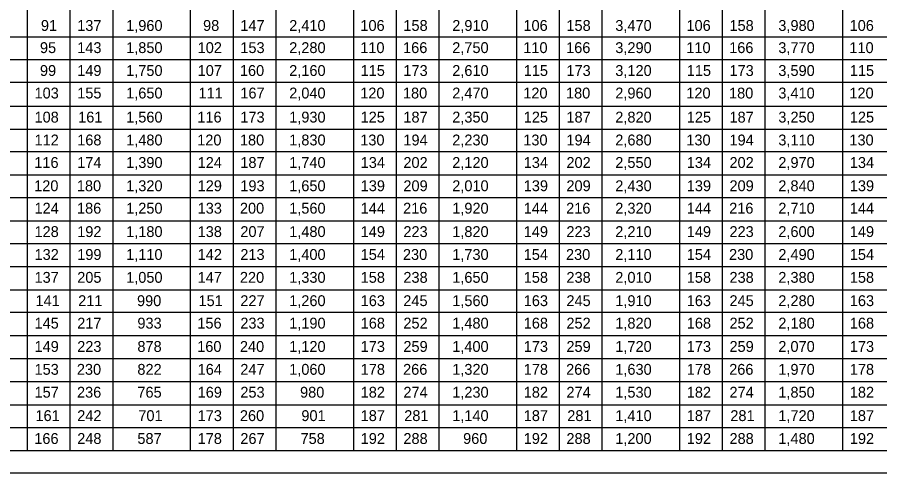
# Model space of a CAD drawing. Extents: x -404.8 to -373.6, y -458.1 to -437.7.
# Drawn here: x -398.05 to -386.16, y -458.05 to -451.76 of the extents above; entities that cross this region are included whole.
import ezdxf

# ---------------------------------------------------------------- set-up
doc = ezdxf.new("R2010")
doc.units = 0
for name, color, linetype in [('Bridge-Named Boundary', 7, 'Continuous'), ('Common-Notes', 7, 'Continuous'), ('Level 4', 7, 'Continuous')]:
    doc.layers.add(name, color=color, linetype=linetype)

msp = doc.modelspace()

# ---------------------------------------------------------------- linework, layer by layer
at = {"layer": 'Bridge-Named Boundary'}
msp.add_lwpolyline([(-404.826, -458.051), (-373.576, -458.051), (-373.576, -437.676), (-404.826, -437.676)], close=True, dxfattribs=at)
at = {"layer": 'Level 4'}
for p, q in [((-396.737, -447.012), (-396.737, -457.744)), ((-394.488, -447.012), (-394.488, -457.744)), ((-392.239, -447.012), (-392.239, -457.744)), ((-389.99, -447.012), (-389.99, -457.744)), ((-387.741, -447.012), (-387.741, -457.744)), ((-397.915, -447.328), (-397.915, -457.744)), ((-397.326, -447.328), (-397.326, -457.744)), ((-395.666, -447.328), (-395.666, -457.744)), ((-395.077, -447.328), (-395.077, -457.744)), ((-393.417, -447.328), (-393.417, -457.744)), ((-392.828, -447.328), (-392.828, -457.744)), ((-391.168, -447.328), (-391.168, -457.744)), ((-390.579, -447.328), (-390.579, -457.744)), ((-388.919, -447.328), (-388.919, -457.744)), ((-388.33, -447.328), (-388.33, -457.744)), ((-386.67, -447.328), (-386.67, -457.744)), ((-404.161, -452.03), (-383.242, -452.03)), ((-404.161, -452.346), (-383.242, -452.346)), ((-404.161, -452.657), (-383.242, -452.657)), ((-404.161, -452.989), (-383.242, -452.989)), ((-404.161, -453.305), (-383.242, -453.305)), ((-404.161, -453.616), (-383.242, -453.616)), ((-404.161, -453.938), (-383.242, -453.938)), ((-404.161, -454.248), (-383.242, -454.248)), ((-404.161, -454.57), (-383.242, -454.57)), ((-404.161, -454.886), (-383.242, -454.886)), ((-404.161, -455.203), (-383.242, -455.203)), ((-404.161, -455.524), (-383.242, -455.524)), ((-404.161, -455.834), (-383.242, -455.834)), ((-404.161, -456.157), (-383.242, -456.157)), ((-404.161, -456.473), (-383.242, -456.473)), ((-404.161, -456.789), (-383.242, -456.789)), ((-404.161, -457.111), (-383.242, -457.111)), ((-404.161, -457.427), (-383.242, -457.427)), ((-404.161, -457.744), (-383.242, -457.744))]:
    msp.add_line(p, q, dxfattribs=at)

# ---------------------------------------------------------------- texts
at = {"layer": 'Common-Notes'}
for s, p in [('91', (-397.727, -451.95)), ('137', (-397.226, -451.95)), ('1,960', (-396.551, -451.95)), ('98', (-395.49, -451.95)), ('147', (-394.976, -451.95)), ('2,410', (-394.302, -451.95)), ('106', (-393.32, -451.95)), ('158', (-392.727, -451.95)), ('2,910', (-392.053, -451.95)), ('106', (-391.071, -451.95)), ('158', (-390.478, -451.95)), ('3,470', (-389.804, -451.95)), ('106', (-388.822, -451.95)), ('158', (-388.229, -451.95)), ('3,980', (-387.555, -451.95)), ('106', (-386.572, -451.95)), ('95', (-397.74, -452.256)), ('143', (-397.226, -452.256)), ('1,850', (-396.551, -452.256)), ('102', (-395.565, -452.256)), ('153', (-394.976, -452.256)), ('2,280', (-394.302, -452.256)), ('110', (-393.322, -452.256)), ('166', (-392.731, -452.256)), ('2,750', (-392.053, -452.256)), ('110', (-391.073, -452.256)), ('166', (-390.482, -452.256)), ('3,290', (-389.804, -452.256)), ('110', (-388.824, -452.256)), ('166', (-388.233, -452.256)), ('3,770', (-387.555, -452.256)), ('110', (-386.575, -452.256)), ('99', (-397.74, -452.572)), ('149', (-397.226, -452.572)), ('1,750', (-396.551, -452.572)), ('107', (-395.565, -452.572)), ('160', (-394.982, -452.572)), ('2,160', (-394.302, -452.572)), ('115', (-393.317, -452.572)), ('173', (-392.727, -452.572)), ('2,610', (-392.053, -452.572)), ('115', (-391.067, -452.572)), ('173', (-390.478, -452.572)), ('3,120', (-389.804, -452.572)), ('115', (-388.818, -452.572)), ('173', (-388.229, -452.572)), ('3,590', (-387.555, -452.572)), ('115', (-386.569, -452.572)), ('103', (-397.815, -452.883)), ('155', (-397.226, -452.883)), ('1,650', (-396.551, -452.883)), ('111', (-395.553, -452.883)), ('167', (-394.976, -452.883)), ('2,040', (-394.302, -452.883)), ('120', (-393.322, -452.883)), ('180', (-392.733, -452.883)), ('2,470', (-392.053, -452.883)), ('120', (-391.073, -452.883)), ('180', (-390.484, -452.883)), ('2,960', (-389.804, -452.883)), ('120', (-388.824, -452.883)), ('180', (-388.235, -452.883)), ('3,410', (-387.555, -452.883)), ('120', (-386.575, -452.883)), ('108', (-397.815, -453.215)), ('161', (-397.213, -453.215)), ('1,560', (-396.551, -453.215)), ('116', (-395.569, -453.215)), ('173', (-394.976, -453.215)), ('1,930', (-394.302, -453.215)), ('125', (-393.317, -453.215)), ('187', (-392.727, -453.215)), ('2,350', (-392.053, -453.215)), ('125', (-391.067, -453.215)), ('187', (-390.478, -453.215)), ('2,820', (-389.804, -453.215)), ('125', (-388.818, -453.215)), ('187', (-388.229, -453.215)), ('3,250', (-387.555, -453.215)), ('125', (-386.569, -453.215)), ('112', (-397.815, -453.531)), ('168', (-397.226, -453.531)), ('1,480', (-396.551, -453.531)), ('120', (-395.571, -453.531)), ('180', (-394.982, -453.531)), ('1,830', (-394.302, -453.531)), ('130', (-393.322, -453.531)), ('194', (-392.727, -453.531)), ('2,230', (-392.053, -453.531)), ('130', (-391.073, -453.531)), ('194', (-390.478, -453.531)), ('2,680', (-389.804, -453.531)), ('130', (-388.824, -453.531)), ('194', (-388.229, -453.531)), ('3,110', (-387.555, -453.531)), ('130', (-386.575, -453.531)), ('116', (-397.818, -453.842)), ('174', (-397.226, -453.842)), ('1,390', (-396.551, -453.842)), ('124', (-395.565, -453.842)), ('187', (-394.976, -453.842)), ('1,740', (-394.302, -453.842)), ('134', (-393.316, -453.842)), ('202', (-392.727, -453.842)), ('2,120', (-392.053, -453.842)), ('134', (-391.067, -453.842)), ('202', (-390.478, -453.842)), ('2,550', (-389.804, -453.842)), ('134', (-388.818, -453.842)), ('202', (-388.229, -453.842)), ('2,970', (-387.555, -453.842)), ('134', (-386.569, -453.842)), ('120', (-397.82, -454.163)), ('180', (-397.231, -454.163)), ('1,320', (-396.551, -454.163)), ('129', (-395.565, -454.163)), ('193', (-394.976, -454.163)), ('1,650', (-394.302, -454.163)), ('139', (-393.316, -454.163)), ('209', (-392.727, -454.163)), ('2,010', (-392.053, -454.163)), ('139', (-391.067, -454.163)), ('209', (-390.478, -454.163)), ('2,430', (-389.804, -454.163)), ('139', (-388.818, -454.163)), ('209', (-388.229, -454.163)), ('2,840', (-387.555, -454.163)), ('139', (-386.569, -454.163)), ('124', (-397.815, -454.473)), ('186', (-397.229, -454.473)), ('1,250', (-396.551, -454.473)), ('133', (-395.565, -454.473)), ('200', (-394.982, -454.473)), ('1,560', (-394.302, -454.473)), ('144', (-393.316, -454.473)), ('216', (-392.731, -454.473)), ('1,920', (-392.053, -454.473)), ('144', (-391.067, -454.473)), ('216', (-390.482, -454.473)), ('2,320', (-389.804, -454.473)), ('144', (-388.818, -454.473)), ('216', (-388.233, -454.473)), ('2,710', (-387.555, -454.473)), ('144', (-386.569, -454.473)), ('128', (-397.815, -454.796)), ('192', (-397.226, -454.796)), ('1,180', (-396.551, -454.796)), ('138', (-395.565, -454.796)), ('207', (-394.976, -454.796)), ('1,480', (-394.302, -454.796)), ('149', (-393.316, -454.796)), ('223', (-392.727, -454.796)), ('1,820', (-392.053, -454.796)), ('149', (-391.067, -454.796)), ('223', (-390.478, -454.796)), ('2,210', (-389.804, -454.796)), ('149', (-388.818, -454.796)), ('223', (-388.229, -454.796)), ('2,600', (-387.555, -454.796)), ('149', (-386.569, -454.796)), ('132', (-397.815, -455.112)), ('199', (-397.226, -455.112)), ('1,110', (-396.551, -455.112)), ('142', (-395.565, -455.112)), ('213', (-394.976, -455.112)), ('1,400', (-394.302, -455.112)), ('154', (-393.316, -455.112)), ('230', (-392.733, -455.112)), ('1,730', (-392.053, -455.112)), ('154', (-391.067, -455.112)), ('230', (-390.484, -455.112)), ('2,110', (-389.804, -455.112)), ('154', (-388.818, -455.112)), ('230', (-388.235, -455.112)), ('2,490', (-387.555, -455.112)), ('154', (-386.569, -455.112)), ('137', (-397.815, -455.428)), ('205', (-397.226, -455.428)), ('1,050', (-396.551, -455.428)), ('147', (-395.565, -455.428)), ('220', (-394.982, -455.428)), ('1,330', (-394.302, -455.428)), ('158', (-393.316, -455.428)), ('238', (-392.727, -455.428)), ('1,650', (-392.053, -455.428)), ('158', (-391.067, -455.428)), ('238', (-390.478, -455.428)), ('2,010', (-389.804, -455.428)), ('158', (-388.818, -455.428)), ('238', (-388.229, -455.428)), ('2,380', (-387.555, -455.428)), ('158', (-386.569, -455.428)), ('141', (-397.802, -455.75)), ('211', (-397.213, -455.75)), ('990', (-396.401, -455.75)), ('151', (-395.553, -455.75)), ('227', (-394.976, -455.75)), ('1,260', (-394.302, -455.75)), ('163', (-393.316, -455.75)), ('245', (-392.728, -455.75)), ('1,560', (-392.053, -455.75)), ('163', (-391.067, -455.75)), ('245', (-390.478, -455.75)), ('1,910', (-389.804, -455.75)), ('163', (-388.818, -455.75)), ('245', (-388.229, -455.75)), ('2,280', (-387.555, -455.75)), ('163', (-386.569, -455.75)), ('145', (-397.815, -456.06)), ('217', (-397.226, -456.06)), ('933', (-396.396, -456.06)), ('156', (-395.569, -456.06)), ('233', (-394.976, -456.06)), ('1,190', (-394.302, -456.06)), ('168', (-393.316, -456.06)), ('252', (-392.727, -456.06)), ('1,480', (-392.053, -456.06)), ('168', (-391.067, -456.06)), ('252', (-390.478, -456.06)), ('1,820', (-389.804, -456.06)), ('168', (-388.818, -456.06)), ('252', (-388.229, -456.06)), ('2,180', (-387.555, -456.06)), ('168', (-386.569, -456.06)), ('149', (-397.815, -456.382)), ('223', (-397.226, -456.382)), ('878', (-396.396, -456.382)), ('160', (-395.571, -456.382)), ('240', (-394.982, -456.382)), ('1,120', (-394.302, -456.382)), ('173', (-393.316, -456.382)), ('259', (-392.727, -456.382)), ('1,400', (-392.053, -456.382)), ('173', (-391.067, -456.382)), ('259', (-390.478, -456.382)), ('1,720', (-389.804, -456.382)), ('173', (-388.818, -456.382)), ('259', (-388.229, -456.382)), ('2,070', (-387.555, -456.382)), ('173', (-386.569, -456.382)), ('153', (-397.815, -456.698)), ('230', (-397.231, -456.698)), ('822', (-396.396, -456.698)), ('164', (-395.565, -456.698)), ('247', (-394.976, -456.698)), ('1,060', (-394.302, -456.698)), ('178', (-393.316, -456.698)), ('266', (-392.731, -456.698)), ('1,320', (-392.053, -456.698)), ('178', (-391.067, -456.698)), ('266', (-390.482, -456.698)), ('1,630', (-389.804, -456.698)), ('178', (-388.818, -456.698)), ('266', (-388.233, -456.698)), ('1,970', (-387.555, -456.698)), ('178', (-386.569, -456.698)), ('157', (-397.815, -457.014)), ('236', (-397.229, -457.014)), ('765', (-396.396, -457.014)), ('169', (-395.565, -457.014)), ('253', (-394.976, -457.014)), ('980', (-394.152, -457.014)), ('182', (-393.316, -457.014)), ('274', (-392.727, -457.014)), ('1,230', (-392.053, -457.014)), ('182', (-391.067, -457.014)), ('274', (-390.478, -457.014)), ('1,530', (-389.804, -457.014)), ('182', (-388.818, -457.014)), ('274', (-388.229, -457.014)), ('1,850', (-387.555, -457.014)), ('182', (-386.569, -457.014)), ('161', (-397.802, -457.337)), ('242', (-397.226, -457.337)), ('701', (-396.383, -457.337)), ('173', (-395.565, -457.337)), ('260', (-394.982, -457.337)), ('901', (-394.134, -457.337)), ('187', (-393.316, -457.337)), ('281', (-392.715, -457.337)), ('1,140', (-392.053, -457.337)), ('187', (-391.067, -457.337)), ('281', (-390.466, -457.337)), ('1,410', (-389.804, -457.337)), ('187', (-388.818, -457.337)), ('281', (-388.217, -457.337)), ('1,720', (-387.555, -457.337)), ('187', (-386.569, -457.337)), ('166', (-397.818, -457.653)), ('248', (-397.226, -457.653)), ('587', (-396.396, -457.653)), ('178', (-395.565, -457.653)), ('267', (-394.976, -457.653)), ('758', (-394.146, -457.653)), ('192', (-393.316, -457.653)), ('288', (-392.727, -457.653)), ('960', (-391.903, -457.653)), ('192', (-391.067, -457.653)), ('288', (-390.478, -457.653)), ('1,200', (-389.804, -457.653)), ('192', (-388.818, -457.653)), ('288', (-388.229, -457.653)), ('1,480', (-387.555, -457.653)), ('192', (-386.569, -457.653))]:
    msp.add_text(s, height=0.15, dxfattribs=at).set_placement(p)

doc.saveas('drawing.dxf')
